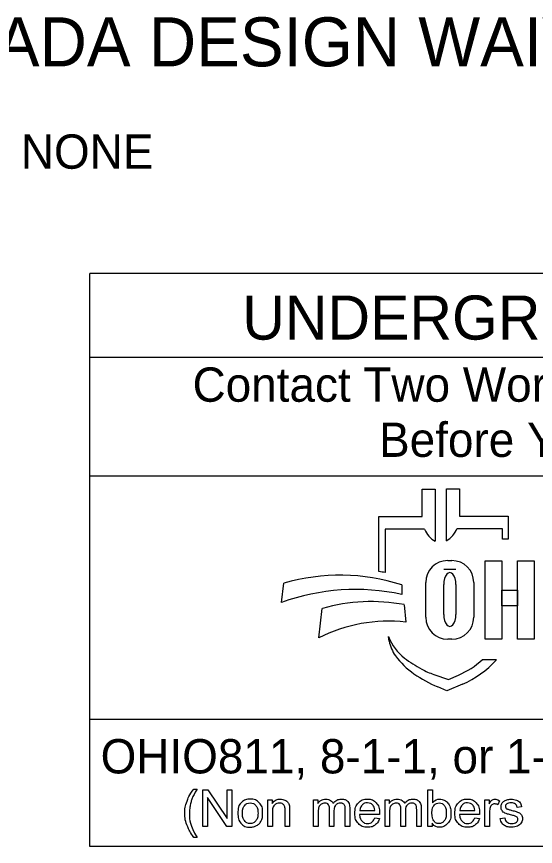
# Model space of a CAD drawing. Extents: x 0 to 34, y 0 to 22.
# Drawn here: x 2.079 to 4.196, y 2.143 to 5.529 of the extents above; entities that cross this region are included whole.
import ezdxf

# ---------------------------------------------------------------- set-up
doc = ezdxf.new("R2010")
doc.units = 0
for name, color, linetype in [('Default', 7, 'Continuous'), ('SH_Data', 7, 'Continuous'), ('SH_Text', 7, 'Continuous')]:
    doc.layers.add(name, color=color, linetype=linetype)

msp = doc.modelspace()

# ---------------------------------------------------------------- linework, layer by layer
at = {"layer": 'SH_Data'}
for p, q in [((2.3775, 2.1428), (2.3775, 4.4803)), ((6.6275, 4.4803), (2.3775, 4.4803)), ((2.3775, 4.1387), (6.6275, 4.1387)), ((2.3775, 3.6553), (6.6275, 3.6553)), ((6.6275, 2.6607), (2.3775, 2.6607)), ((6.6275, 2.1428), (2.3775, 2.1428))]:
    msp.add_line(p, q, dxfattribs=at)
at = {"layer": 'SH_Text'}
for p, q in [((3.7335, 3.4883), (3.7335, 3.5998)), ((3.7335, 3.5998), (3.7872, 3.5998)), ((3.7872, 3.5998), (3.7872, 3.3877)), ((3.8329, 3.39), (3.8329, 3.6021)), ((3.8329, 3.6021), (3.8865, 3.6021)), ((3.8865, 3.6021), (3.8865, 3.4906)), ((3.5576, 3.2644), (3.5576, 3.4883)), ((3.5576, 3.4883), (3.7335, 3.4883)), ((3.8865, 3.4906), (4.0857, 3.4906)), ((4.0857, 3.4906), (4.0857, 3.3968)), ((3.5828, 3.4369), (3.5828, 3.26)), ((3.7439, 3.4369), (3.5828, 3.4369)), ((4.0625, 3.4392), (3.8761, 3.4392)), ((4.0625, 3.3968), (4.0625, 3.4392)), ((4.0857, 3.3968), (4.0625, 3.3968)), ((3.8385, 3.3091), (3.8551, 3.3091)), ((3.8718, 3.2721), (3.822, 3.2721)), ((3.7491, 3.0776), (3.7491, 3.2196)), ((3.9445, 3.2196), (3.9445, 3.0776)), ((3.1602, 3.1381), (3.1696, 3.2162)), ((3.6509, 3.2097), (3.6509, 3.1709)), ((3.822, 3.089), (3.822, 3.2114)), ((3.8718, 3.2114), (3.8718, 3.089)), ((3.6608, 3.1291), (3.6671, 3.0582)), ((3.312, 2.9936), (3.3267, 3.1137)), ((3.5997, 2.9807), (3.5967, 2.9986)), ((3.8551, 2.9882), (3.8385, 2.9882)), ((3.98, 2.9048), (4.0375, 2.9048)), ((3.7816, 2.8444), (3.841, 2.8239)), ((3.841, 2.8239), (3.8821, 2.8417)), ((3.835, 2.7769), (3.7976, 2.7934)), ((3.8983, 2.8044), (3.835, 2.7769))]:
    msp.add_line(p, q, dxfattribs=at)
for points in [[(3.991, 3.3081), (4.0589, 3.3081), (4.0589, 2.9881), (3.991, 2.9881)], [(4.1231, 3.3081), (4.1911, 3.3081), (4.1911, 2.9881), (4.1231, 2.9881)], [(4.0589, 3.1882), (4.1231, 3.1882), (4.1231, 3.1242), (4.0589, 3.1242)]]:
    msp.add_lwpolyline(points, close=True, dxfattribs=at)
for points in [[(2.8021, 2.3766), (2.8153, 2.3766)], [(2.8389, 2.2239), (2.8389, 2.3741), (2.8592, 2.3741), (2.9382, 2.2561), (2.9382, 2.3741), (2.9572, 2.3741), (2.9572, 2.2239), (2.9369, 2.2239), (2.8579, 2.3419), (2.8579, 2.2239), (2.8389, 2.2239)], [(3.7743, 2.2239), (3.7573, 2.2239), (3.7573, 2.3741), (3.7757, 2.3741), (3.7757, 2.3206)], [(3.1048, 2.2239), (3.1048, 2.3328), (3.1214, 2.3328), (3.1214, 2.3173)], [(3.2912, 2.2239), (3.2912, 2.3328), (3.3077, 2.3328), (3.3077, 2.3174)], [(3.5826, 2.2239), (3.5826, 2.3328), (3.5991, 2.3328), (3.5991, 2.3174)], [(3.9904, 2.2239), (3.9904, 2.3328), (4.007, 2.3328), (4.007, 2.3163)], [(4.0495, 2.3293), (4.043, 2.3122)], [(4.1394, 2.3046), (4.1213, 2.3022)], [(3.1233, 2.2833), (3.1233, 2.2239), (3.1048, 2.2239)], [(3.1932, 2.2908), (3.1932, 2.2239), (3.1748, 2.2239), (3.1748, 2.2901)], [(3.3097, 2.2803), (3.3097, 2.2239), (3.2912, 2.2239)], [(3.3743, 2.2871), (3.3743, 2.2239), (3.3559, 2.2239), (3.3559, 2.2946)], [(3.4388, 2.2986), (3.4388, 2.2239), (3.4203, 2.2239), (3.4203, 2.2924)], [(3.56, 2.2736), (3.4788, 2.2736)], [(3.4799, 2.2887), (3.5406, 2.2887)], [(3.601, 2.2803), (3.601, 2.2239), (3.5826, 2.2239)], [(3.6657, 2.2871), (3.6657, 2.2239), (3.6473, 2.2239), (3.6473, 2.2946)], [(3.7301, 2.2986), (3.7301, 2.2239), (3.7117, 2.2239), (3.7117, 2.2924)], [(3.968, 2.2736), (3.8868, 2.2736)], [(3.8879, 2.2887), (3.9486, 2.2887)], [(4.0088, 2.2809), (4.0088, 2.2239), (3.9904, 2.2239)], [(3.5404, 2.2591), (3.5595, 2.2567)], [(3.7743, 2.2375), (3.7743, 2.2239)], [(3.9484, 2.2591), (3.9675, 2.2567)], [(4.053, 2.2564), (4.0712, 2.2593)], [(2.8153, 2.1798), (2.8021, 2.1798)]]:
    msp.add_lwpolyline(points, dxfattribs=at)
for centre, radius, start, end in [((3.8353, 3.4736), 0.0985, 201.9296, 240.7469), ((3.7847, 3.476), 0.0985, 299.2531, 338.0704), ((3.8385, 3.2196), 0.0895, 90, 180), ((3.8551, 3.2196), 0.0895, 0, 90), ((3.4295, 2.4554), 0.8191, 79.2074, 81.0007), ((3.3997, 2.4302), 0.8191, 72.1402, 106.3144), ((3.4628, 2.2991), 0.8919, 77.8238, 109.8274), ((3.5267, 2.4094), 0.7322, 79.44, 105.8467), ((3.5987, 2.4262), 0.6357, 83.8248, 116.8021), ((3.8385, 3.0776), 0.0895, 180, 270), ((3.8551, 3.0776), 0.0895, 270, 0), ((3.7841, 3.0707), 0.2008, 201.0457, 232.5314), ((3.741, 3.0048), 0.1433, 189.6817, 216.0884), ((3.8747, 3.1022), 0.3088, 216.0884, 235.7167), ((3.9766, 3.3219), 0.5173, 232.5314, 241.794), ((3.7387, 3.1722), 0.3602, 293.4582, 312.0712), ((3.7387, 3.1722), 0.401, 293.4582, 317.8286), ((4.0412, 3.3465), 0.6044, 235.7167, 246.2325), ((3.8914, 3.1631), 0.3371, 241.794, 250.9821)]:
    msp.add_arc(centre, radius, start, end, dxfattribs=at)
for centre, start_param, end_param in [((3.8469, 3.2114), 4.712389, 7.853982), ((3.8469, 3.089), 1.570796, 4.712389)]:
    msp.add_ellipse(centre, major_axis=(0, 0.0484), ratio=0.514403, start_param=start_param, end_param=end_param, dxfattribs=at)
for points in [[(2.8021, 2.1798), (2.7869, 2.199), (2.7763, 2.2248), (2.7657, 2.2506), (2.7657, 2.2783), (2.7657, 2.3026), (2.7736, 2.325), (2.7829, 2.3509), (2.8021, 2.3766)], [(2.8153, 2.3766), (2.8029, 2.3553), (2.7989, 2.3462), (2.7927, 2.332), (2.7891, 2.3167), (2.7847, 2.2975), (2.7847, 2.2782), (2.7847, 2.2289), (2.8153, 2.1798)], [(2.9814, 2.2783), (2.9814, 2.3085), (2.9981, 2.3231), (3.0122, 2.3352), (3.0323, 2.3352), (3.0547, 2.3352), (3.069, 2.3205), (3.0832, 2.3058), (3.0832, 2.2799), (3.0832, 2.2589), (3.0769, 2.2469), (3.0706, 2.2348), (3.0586, 2.2282), (3.0466, 2.2215), (3.0323, 2.2215), (3.0095, 2.2215), (2.9954, 2.2362), (2.9814, 2.2508), (2.9814, 2.2783)], [(3.0003, 2.2783), (3.0003, 2.2574), (3.0094, 2.247), (3.0185, 2.2366), (3.0323, 2.2366), (3.046, 2.2366), (3.0551, 2.2471), (3.0642, 2.2575), (3.0642, 2.279), (3.0642, 2.2991), (3.0551, 2.3095), (3.0459, 2.3199), (3.0323, 2.3199), (3.0185, 2.3199), (3.0094, 2.3096), (3.0003, 2.2992), (3.0003, 2.2783)], [(3.1214, 2.3173), (3.1334, 2.3352), (3.156, 2.3352), (3.1659, 2.3352), (3.1741, 2.3316), (3.1823, 2.3281), (3.1864, 2.3224), (3.1905, 2.3166), (3.1922, 2.3087), (3.1932, 2.3036), (3.1932, 2.2908)], [(3.1748, 2.2901), (3.1748, 2.3013), (3.1726, 2.3069), (3.1705, 2.3125), (3.165, 2.3158), (3.1595, 2.3191), (3.1521, 2.3191), (3.1404, 2.3191), (3.1318, 2.3117), (3.1233, 2.3042), (3.1233, 2.2833)], [(3.3077, 2.3174), (3.3128, 2.3254), (3.3214, 2.3303), (3.3299, 2.3352), (3.3407, 2.3352), (3.3528, 2.3352), (3.3606, 2.3301), (3.3683, 2.3251), (3.3715, 2.3161), (3.3844, 2.3352), (3.4051, 2.3352), (3.4213, 2.3352), (3.43, 2.3262), (3.4388, 2.3172), (3.4388, 2.2986)], [(3.3559, 2.2946), (3.3559, 2.3069), (3.3514, 2.313), (3.3469, 2.3191), (3.3366, 2.3191), (3.3288, 2.3191), (3.3222, 2.315), (3.3156, 2.311), (3.3126, 2.3031), (3.3097, 2.2952), (3.3097, 2.2803)], [(3.4203, 2.2924), (3.4203, 2.3035), (3.4185, 2.3083), (3.4168, 2.3132), (3.412, 2.3162), (3.4073, 2.3191), (3.401, 2.3191), (3.3895, 2.3191), (3.3819, 2.3115), (3.3743, 2.3039), (3.3743, 2.2871)], [(3.5595, 2.2567), (3.555, 2.24), (3.5428, 2.2307), (3.5306, 2.2215), (3.5117, 2.2215), (3.4878, 2.2215), (3.4738, 2.2362), (3.4598, 2.2509), (3.4598, 2.2774), (3.4598, 2.3049), (3.474, 2.32), (3.4881, 2.3352), (3.5106, 2.3352), (3.5324, 2.3352), (3.5463, 2.3203), (3.5601, 2.3055), (3.5601, 2.2785), (3.5601, 2.2769), (3.56, 2.2736)], [(3.5406, 2.2887), (3.5394, 2.3025), (3.5337, 2.3094), (3.5249, 2.3201), (3.5108, 2.3201), (3.4981, 2.3201), (3.4894, 2.3115), (3.4808, 2.303), (3.4799, 2.2887)], [(3.5991, 2.3174), (3.6042, 2.3254), (3.6127, 2.3303), (3.6212, 2.3352), (3.6321, 2.3352), (3.6442, 2.3352), (3.6519, 2.3301), (3.6597, 2.3251), (3.6628, 2.3161), (3.6758, 2.3352), (3.6965, 2.3352), (3.7127, 2.3352), (3.7214, 2.3262), (3.7301, 2.3172), (3.7301, 2.2986)], [(3.6473, 2.2946), (3.6473, 2.3069), (3.6428, 2.313), (3.6383, 2.3191), (3.628, 2.3191), (3.6202, 2.3191), (3.6136, 2.315), (3.607, 2.311), (3.604, 2.3031), (3.601, 2.2952), (3.601, 2.2803)], [(3.7117, 2.2924), (3.7117, 2.3035), (3.7099, 2.3083), (3.7081, 2.3132), (3.7034, 2.3162), (3.6987, 2.3191), (3.6923, 2.3191), (3.6809, 2.3191), (3.6733, 2.3115), (3.6657, 2.3039), (3.6657, 2.2871)], [(3.7741, 2.2792), (3.7741, 2.2596), (3.7794, 2.2509), (3.7881, 2.2366), (3.8029, 2.2366), (3.815, 2.2366), (3.8238, 2.2471), (3.8326, 2.2576), (3.8326, 2.2784), (3.8326, 2.2998), (3.8241, 2.3099), (3.8157, 2.3201), (3.8038, 2.3201), (3.7917, 2.3201), (3.7829, 2.3096), (3.7741, 2.299), (3.7741, 2.2792)], [(3.7757, 2.3206), (3.7874, 2.3352), (3.8055, 2.3352), (3.8155, 2.3352), (3.8245, 2.3311), (3.8335, 2.3271), (3.8392, 2.3198), (3.845, 2.3124), (3.8483, 2.3021), (3.8516, 2.2918), (3.8516, 2.28), (3.8516, 2.252), (3.8378, 2.2368), (3.8239, 2.2215), (3.8046, 2.2215), (3.7853, 2.2215), (3.7743, 2.2375)], [(3.9675, 2.2567), (3.963, 2.24), (3.9508, 2.2307), (3.9386, 2.2215), (3.9196, 2.2215), (3.8958, 2.2215), (3.8818, 2.2362), (3.8678, 2.2509), (3.8678, 2.2774), (3.8678, 2.3049), (3.882, 2.32), (3.8961, 2.3352), (3.9186, 2.3352), (3.9404, 2.3352), (3.9543, 2.3203), (3.9681, 2.3055), (3.9681, 2.2785), (3.9681, 2.2769), (3.968, 2.2736)], [(3.9486, 2.2887), (3.9474, 2.3025), (3.9417, 2.3094), (3.9328, 2.3201), (3.9188, 2.3201), (3.9061, 2.3201), (3.8974, 2.3115), (3.8888, 2.303), (3.8879, 2.2887)], [(4.007, 2.3163), (4.0133, 2.3278), (4.0187, 2.3315), (4.0241, 2.3352), (4.0305, 2.3352), (4.0398, 2.3352), (4.0495, 2.3293)], [(4.043, 2.3122), (4.0363, 2.3162), (4.0295, 2.3162), (4.0235, 2.3162), (4.0187, 2.3125), (4.0139, 2.3089), (4.0119, 2.3024), (4.0088, 2.2926), (4.0088, 2.2809)], [(4.1213, 2.3022), (4.1201, 2.3106), (4.1142, 2.3153), (4.1083, 2.3201), (4.0975, 2.3201), (4.0848, 2.3201), (4.0794, 2.3159), (4.0739, 2.3116), (4.0739, 2.306), (4.0739, 2.3024), (4.0762, 2.2995), (4.0785, 2.2966), (4.0833, 2.2946), (4.086, 2.2936), (4.0996, 2.2899), (4.1192, 2.2847), (4.1269, 2.2813), (4.1347, 2.278), (4.1391, 2.2717), (4.1435, 2.2653), (4.1435, 2.2559), (4.1435, 2.2467), (4.1381, 2.2386), (4.1327, 2.2304), (4.1226, 2.226), (4.1124, 2.2215), (4.0996, 2.2215), (4.0784, 2.2215), (4.0672, 2.2303), (4.0561, 2.2391), (4.053, 2.2564)], [(4.0712, 2.2593), (4.0727, 2.2483), (4.0798, 2.2425), (4.0868, 2.2366), (4.0995, 2.2366), (4.1122, 2.2366), (4.1184, 2.2418), (4.1245, 2.247), (4.1245, 2.254), (4.1245, 2.2602), (4.1191, 2.2638), (4.1153, 2.2663), (4.1002, 2.2701), (4.0799, 2.2752), (4.072, 2.2789), (4.0642, 2.2827), (4.0601, 2.2893), (4.0561, 2.2959), (4.0561, 2.3038), (4.0561, 2.3111), (4.0594, 2.3173), (4.0628, 2.3235), (4.0685, 2.3276), (4.0728, 2.3308), (4.0803, 2.333), (4.0877, 2.3352), (4.0962, 2.3352), (4.109, 2.3352), (4.1187, 2.3315), (4.1284, 2.3278), (4.133, 2.3215), (4.1377, 2.3152), (4.1394, 2.3046)], [(3.4788, 2.2736), (3.4799, 2.2557), (3.489, 2.2462), (3.4981, 2.2366), (3.5117, 2.2366), (3.5219, 2.2366), (3.5291, 2.242), (3.5362, 2.2473), (3.5404, 2.2591)], [(3.8868, 2.2736), (3.8879, 2.2557), (3.897, 2.2462), (3.9061, 2.2366), (3.9197, 2.2366), (3.9299, 2.2366), (3.937, 2.242), (3.9442, 2.2473), (3.9484, 2.2591)]]:
    msp.add_open_spline(points, degree=3, dxfattribs=at)

# ---------------------------------------------------------------- texts
at = {"layer": 'Default'}
msp.add_text('NONE', height=0.14, dxfattribs=at).set_placement((2.0965, 4.9079))
at = {"layer": 'SH_Text'}
for s, height, p in [('ADA DESIGN WAIVERS', 0.2, (1.9944, 5.3256)), ('UNDERGROUND UTILITIES', 0.18, (3, 4.2106)), ('Contact Two Working Days', 0.14, (2.7972, 3.9571)), ('Before You Dig', 0.14, (3.5583, 3.7321)), ('OHIO811, 8-1-1, or 1-800-362-2764', 0.14, (2.422, 2.4406))]:
    msp.add_text(s, height=height, dxfattribs=at).set_placement(p)

doc.saveas('drawing.dxf')
